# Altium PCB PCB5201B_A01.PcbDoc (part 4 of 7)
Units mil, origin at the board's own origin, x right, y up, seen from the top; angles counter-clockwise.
Board outline 4527.56 x 2362.2 mil, 6 copper layers (Top Layer, GND Layer 2, Signal Layer 3, Signal Layer 4, VCC Layer 5, Bottom Layer), stack 61.221 mil thick; 361 components, 250 nets, 1223 pads, 1068 vias.
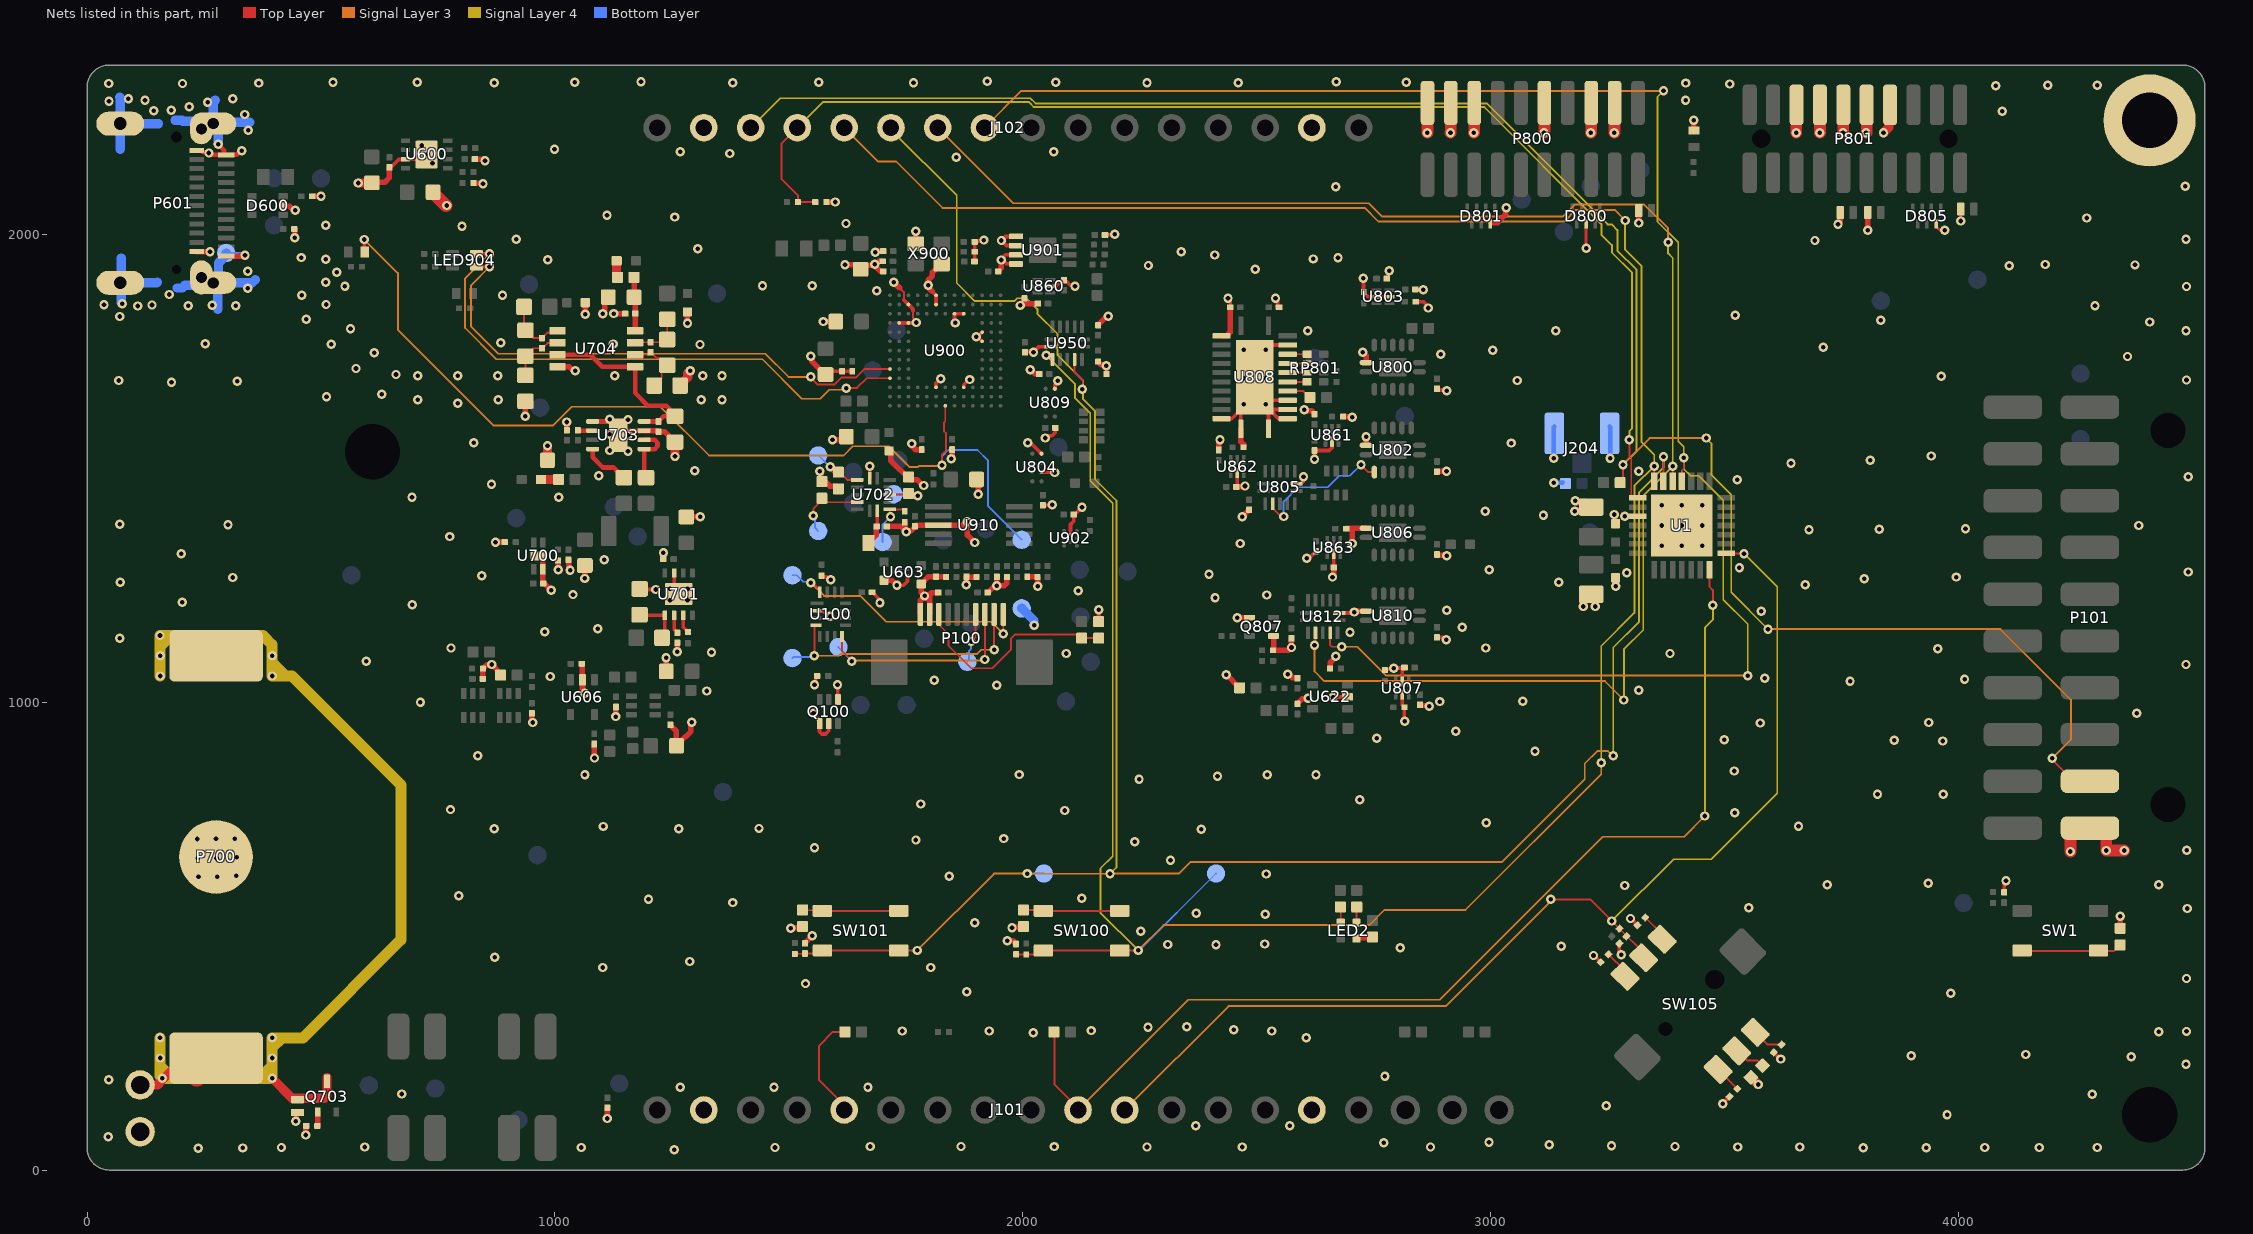
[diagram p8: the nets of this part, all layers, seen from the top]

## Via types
v1: diameter 20, hole 9.84, Top Layer to Bottom Layer, tented both sides, 1068 vias

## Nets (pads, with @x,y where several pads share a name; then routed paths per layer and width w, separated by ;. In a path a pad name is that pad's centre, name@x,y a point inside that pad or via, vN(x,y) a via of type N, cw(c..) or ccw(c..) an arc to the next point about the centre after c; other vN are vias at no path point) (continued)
GND: C1.2 C2.2 C3.2 C4.2 C8.2 C102.2 C103.2 C104.2 C106.2 C143.2 C144.2 C600.2 C602.2 C607.2 C608.2 C609.2 C610.2 C611.2 C621.2 C625.2 C632.2 C635.2 C638.2 C641.2 C652.2 C653.2 C655.2 C660.2 C673.2 C674.2 C700.2 C701.2 C702.2 C703.2 C705.2 C706.2 C707.2 C708.2 C714.2 C720.2 C724.2 C728.2 C729.2 C730.2 C731.2 C800.2 C803.2 C804.2 C805.2 C806.2 C807.2 C808.2 C809.2 C810.2 C827.2 C828.2 C860.2 C861.2 C862.2 C863.2 C864.2 C865.2 C866.2 C867.2 C868.2 C869.2 C870.2 C900.2 C901.2 C902.2 C903.2 C904.2 C905.2 C906.2 C907.2 C908.2 C909.2 C910.2 C911.2 C914.2 C921.2 C922.2 C924.2 C925.2 C926.2 C927.2 C950.2 C951.2 D600.2 D703.2 D800.6 D801.7 D805.7 D806.2 D807.2 D808.2 D809.2 J101.2 J101.15 J102.2 J102.15 J204.2 J204.3 LED900.2 M1.1 P100.1 P100.2 P101.1 P601.25@70.87,2237.01 P601.26@70.87,1896.85 P601.27@244.09,2225.39 P601.27@269.69,2237.01 P601.28@244.09,1908.46 P601.28@269.69,1896.85 P601.A1 P601.A12 P601.B1 P601.B12 P700.2 P800.3 P800.5 P800.9 P800.15 P800.17 P800.19 P801.7 P801.9 P801.11 P801.13 P801.15 Q100.1 Q100.4 Q100.5 Q807.1 Q807.4 R7.1 R104.2 R105.2 R113.1 R124.1 R125.1 R126.1 R127.1 R140.1 R141.1 R146.1 R220.1 R302.1 R602.1 R620.1 R621.1 R623.1 R628.2 R631.1 R634.1 R637.1 R640.1 R674.2 R688.2 R691.2 R703.1 R705.1 R706.1 R707.1 R708.1 R718.1 R760.1 R763.1 R767.1 R771.1 R792.1 R807.2 R808.2 R814.1 R817.1 R839.1 R850.1 R851.1 R852.1 R853.1 R930.2 R931.2 R950.2 R981.2 ST701.1 TPJ614.1 TPJ913.1 U1.3 U1.29 U100.2 U600.3 U600.9 U603.A1 U606.2 U622.2 U700.2 U700.5 U701.3 U701.9 U702.7 U703.3 U703.5 U703.9 U704.4 U800.7 U802.7 U803.2 U803.5 U804.B1 U804.D1 U805.7 U806.7 U807.2 U807.5 U808.2 U808.11 U808.12 U808.13 U808.14 U808.15 U808.16 U808.22 U808.25 U809.D1 U810.7 U812.7 U860.2 U861.2 U862.2 U863.2 U900.C5 U900.C8 U900.H3 U900.J3 U900.K11 U900.K12 U900.L5 U900.L6 U900.M8 U900.M11 U900.N8 U901.1 U901.2 U901.3 U901.4 U902.B2 U910.3 U950.7 X900.2 X900.4 | length 9104.5
  Top Layer w3.94: 1737.2,1885.83 1746.06,1876.97 1746.06,1860.24 ; 1765.75,1837.57 1765.75,1821.85 v1@1772.64,1814.96
  Top Layer w5.91: v1(3204.72,1970.47) D800.6@3204.72,2023.03 ; D805.7@3952.76,2023.03 3952.76,2017.72 3960.63,2009.84 v1@3978.35,2009.84
  Top Layer w7.87: C600.2@646.33,2143.75 646.33,2144.54 648.7,2146.9 652.81,2146.9 666.24,2160.33 679.42,2160.33 U600.3@680.4,2161.32 U600.9@715.84,2161.32 ; R703.1@1185.22,1242.35 1186.43,1241.14 v1(1215.55,1241.14) ; U701.9@1249.02,1243.11 1254.92,1249.02 U701.3@1254.92,1276.57 ; v1(1552.99,976.38) 1552.99,973.18 1565.94,960.23 Q100.4@1565.94,954.32 1565.94,937.01 1570.87,932.09 1578.73,932.09 1585.62,938.98 Q100.5@1585.62,954.32 ; v1(1555.03,1037.53) 1555.03,1040.81 1557.96,1043.74 1557.96,1054.02 1560.32,1056.38 R141.1@1560.71,1056.38 ; U100.2@1558.66,1195.87 1573.05,1195.87 1585.07,1183.85 v1(1588.35,1183.85) ; R140.1@1570.4,1270.69 1570.4,1270.29 1572.76,1267.93 1581.03,1267.93 1586.87,1262.08 v1(1590.16,1262.08) ; C907.2@1578.74,1700.79 1585.63,1707.68 C924.2@1614.17,1707.68 C925.2@1635.83,1707.68 ; v1(1604.33,1037.39) 1604.82,1036.9 1604.82,1005.99 Q100.1@1605.31,1005.5 ; U702.7@1673.23,1478.74 v1(1673.23,1504.92) v1@1679.13,1504.92 ; C104.2@1678.07,1235.18 1678.86,1235.18 1692.63,1221.41 1692.63,1215.07 v1(1694.95,1212.75) ; v1(1731.3,1250) 1745.08,1250 1753.94,1258.86 U603.A1@1753.94,1269.69 ; U900.K12@1736.22,1811.02 U900.K11@1755.91,1811.02 1771.65,1811.02 v1(1772.64,1812.01) v1@1772.64,1814.96 ; 1746.06,1860.24 U900.M11@1755.91,1850.39 1765.75,1840.55 1765.75,1837.57 ; v1@1785.43,1460.63 v1(1788.39,1463.58) ; 1806.5,1878.35 1814.76,1870.08 U900.N8@1814.96,1870.08 U900.M8@1814.96,1850.39 ; U900.C8@1814.96,1673.23 1814.96,1682.09 v1(1824.8,1691.93) ; v1(1856.3,1811.02) 1854.33,1812.99 U900.L6@1854.33,1830.71 U900.L5@1874.02,1830.71 ; U900.C5@1874.02,1673.23 1874.02,1679.13 v1@1884.84,1689.96 ; C910.2@1897.01,1942.24 1897.37,1942.6 1897.37,1962.86 R930.2@1897.68,1963.17 ; R930.2@1897.72,1963.13 R930.2@1897.68,1963.17 ; v1@1898.57,1781.5 v1(1900.59,1781.5) 1901.58,1781.5 v1@1902.56,1782.48 ; U900.H3@1913.39,1771.65 v1@1902.56,1782.48 ; U900.J3@1913.39,1791.34 1904.53,1782.48 v1@1902.56,1782.48 ; v1(1917.32,1988.19) 1915.35,1986.22 1899.61,1986.22 R931.2@1897.64,1984.25 1897.68,1984.21 R930.2@1897.68,1963.17 ; v1@1954.72,1944.88 1958.01,1944.88 1965.48,1937.41 1985.6,1937.41 U901.4@1986.01,1937.01 ; v1@1954.72,1948.16 1963.25,1956.69 U901.3@1986.01,1956.69 ; U901.2@1986.01,1976.38 1985.68,1976.7 1965.23,1976.7 v1(1954.72,1987.2) 1963.26,1995.74 1985.68,1995.74 U901.1@1986.01,1996.06 ; C911.2@2004.92,1748.03 2005.91,1747.05 2007.59,1747.05 2010.55,1750 2021.86,1750 v1(2023.31,1748.56) ; v1@2016.73,1553.15 2018.7,1553.15 U804.D1@2040.35,1531.5 ; v1@2023.62,1750 2024.14,1750 2033.98,1759.84 U950.7@2060.63,1759.84 ; U804.B1@2040.35,1492.13 2067.91,1492.13 v1(2068.9,1491.14) ; C804.2@2043.31,1421.26 2062.01,1421.26 v1(2062.99,1422.24) ; v1(2048.23,1564.96) 2053.15,1569.88 2062.99,1569.88 2069.88,1576.77 C810.2@2069.88,1586.61 ; U860.2@2059.06,1889.76 2071.85,1889.76 2084.65,1902.56 C862.2@2088.58,1902.56 2088.58,1901.77 2090.94,1899.41 2094.25,1899.41 2102,1891.66 2109.69,1891.66 v1(2112.01,1889.34) ; U809.D1@2068.9,1670.28 2069.12,1670.5 2069.12,1678.36 2075.16,1684.4 v1(2075.16,1687.68) ; U902.B2@2102.36,1358.27 2102.36,1379.92 2109.25,1386.81 C914.2@2109.25,1399.61 ; C914.2@2109.25,1401.57 C914.2@2109.25,1399.61 ; v1(2126.97,1417.32) C914.2@2109.25,1399.61 ; C951.2@2176.08,1999.15 2176.77,1999.85 2196.34,1999.85 v1(2197.04,2000.55) ; R981.2@2179.13,1701.77 v1(2179.15,1719.66) ; U808.11@2425.39,1606.3 2446.85,1606.3 U808.25@2466.54,1625.98 ; v1(2438.98,1864.17) 2443.9,1859.25 C808.2@2443.9,1844.49 ; C860.2@2456.69,1460.63 2458.66,1462.6 U862.2@2458.66,1490.16 ; U808.12@2466.54,1584.84 U808.25@2466.54,1625.98 ; U808.25@2497.05,1753.94 2506.89,1763.78 U808.22@2566.73,1763.78 ; U808.13@2525.59,1584.84 U808.25@2525.59,1625.98 ; v1(2540.63,1863.98) 2540.63,1861.23 2545.08,1856.79 2545.08,1846.85 2547.44,1844.49 C806.2@2548.23,1844.49 ; U808.14@2566.73,1606.3 2547.24,1606.3 U808.25@2527.56,1625.98 ; U808.15@2566.73,1625.98 U808.25@2527.56,1625.98 ; U808.16@2566.73,1645.67 2504.92,1645.67 U808.25@2496.06,1636.81 ; U805.7@2585.04,1467.32 2595.28,1467.32 2599.41,1471.46 2599.41,1481.3 v1(2600.39,1482.28) ; v1(2607.28,1308.07) 2612.2,1308.07 C867.2@2626.97,1322.83 ; v1(2624.02,1519.69) C864.2@2624.02,1538.39 2655.51,1538.39 2661.42,1544.29 U861.2@2661.42,1557.09 ; v1(2663.67,1011.11) 2664.02,1011.46 2694.53,1011.46 U622.2@2694.88,1011.81 ; C866.2@2665.35,1288.39 U863.2@2665.35,1316.93 ; U812.7@2676.58,1190.94 2706.69,1190.94 v1(2708.66,1192.91) ; v1(2728.35,1906.5) 2728.84,1906 2728.84,1877.46 R807.2@2729.33,1876.97 ; R807.2@2731.69,1873.62 2738.19,1867.13 U803.2@2756.89,1867.13 ; U803.2@2758.86,1867.13 U803.5@2784.45,1867.13 ; R808.2@2774.61,1068.9 2776.57,1070.87 2788.39,1070.87 v1@2790.35,1072.83 ; C869.2@2778.31,1905.63 2778.78,1905.63 2781.14,1907.99 2781.14,1919.92 v1(2783.46,1922.24) ; v1(2793.31,1072.83) 2793.98,1073.5 2815.83,1073.5 C870.2@2816.5,1074.17 ; U807.5@2811.54,1016.73 2811.54,993.66 2815.04,990.16 R814.1@2816.93,990.16 ; U807.2@2811.54,1044.29 2811.54,1070 2813.39,1071.85 C870.2@2816.93,1071.85 ; R814.1@2816.22,989.37 2816.22,960.42 v1(2816.93,959.71) ; C807.2@2839.57,1882.87 2840.15,1882.29 2856.11,1882.29 v1(2856.69,1881.71) ; R817.1@2840.55,1856.3 2856.91,1856.3 2867.13,1846.09 v1(2867.13,1842.9) ; C827.2@2885.83,1138.78 2900.59,1138.78 v1(2905.51,1133.86) ; C803.2@2885.83,1670.28 2885.83,1670.1 2888.19,1667.74 2905.09,1667.74 v1(2906.5,1666.34) ; v1@2905.61,1493.63 v1(2906.13,1494.14) ; v1(3220.47,458.66) 3221.49,458.66 R124.1@3235.74,444.4 ; C106.2@3275.81,484.47 3275.81,464.35 v1(3279.53,460.63) ; v1(3299.49,537.68) 3300.5,537.68 R127.1@3314.76,523.42 ; v1(3497.08,141.73) 3497.08,142.75 R125.1@3511.33,157 ; R126.1@3605.82,251.49 3620.08,237.23 v1(3621.09,237.23) ; v1@4005.87,2028.91 D808.2@4005.84,2054.37 ; C8.2@4098.43,593.5 4098.43,614.17 v1(4102.36,618.11) ; U808.25@2466.54,1625.98 2477.36,1636.81 U808.25@2496.06,1636.81 ; U808.25@2496.06,1636.81 2506.89,1625.98 U808.25@2525.59,1625.98 ; U808.25@2525.59,1625.98 U808.25@2527.56,1625.98
  Top Layer w9.84: P601.B12@234.25,2180.12 234.65,2179.72 245.08,2179.72 248.56,2176.24 258.51,2176.24 v1(260.45,2174.3) ; v1@262.14,2172.36 265.14,2172.36 266.83,2170.67 P601.A1@292.6,2170.67 ; v1(280.64,2193.3) 280.64,2192.48 292.6,2180.51 P601.A1@292.6,2170.67 ; v1(330.62,2179.03) 327.87,2179.03 319.51,2170.67 297.64,2170.67 P601.A1@297.24,2170.28 ; U703.5@1080.71,1600.39 v1@1112.21,1600.39 ; R302.1@1580.54,2069.45 1580.63,2069.54 1599.07,2069.54 v1(1599.17,2069.64) 1596.46,2072.35 v1@1596.46,2072.83 ; v1@2162.4,1196.85 2162.72,1196.53 2162.72,1172.56 R146.1@2162.68,1172.52 ; C868.2@2849.45,994.61 2850.83,993.23 2867.68,993.23 v1(2869.09,991.81) ; C3.2@3198.82,1217.3 3212.6,1231.08 C3.2@3215.55,1231.08 ; C1.2@3216.51,1410.41 C1.2@3231.3,1425.2 ; C3.2@3224.41,1224.41 C3.2@3225.39,1225.39 ; v1(3267.72,1248.03) C4.2@3267.72,1266.21 ; v1(3287.4,1397.64) U1.3@3319.88,1397.64 ; P601.A1@292.6,2170.67 296.85,2170.67 P601.A1@297.24,2170.28 ; P601.A1@292.6,2170.67 293,2170.28 P601.A1@297.24,2170.28
  Top Layer w10.63: v1@3033.74,2054.91 v1(3033.74,2057.12)
  Top Layer w11.81: P601.B1@234.25,1963.58 v1(262.8,1963.58) ; P601.A12@297.24,1953.74 324.8,1953.74 325.2,1954.14 336.03,1954.14 v1(337.6,1955.71) ; D600.2@419.16,2061.96 420.64,2060.48 432.81,2060.48 441.24,2052.05 v1(444.79,2052.05) ; R621.1@442.91,2011.81 443.01,2011.81 443.41,2011.42 443.41,1993.6 v1(443.9,1993.11) ; v1(445.87,104.33) 447.43,105.9 447.43,121.06 449.4,123.03 D703.2@449.8,123.03 ; v1(467.52,74.8) 467.82,75.1 467.82,94.09 468.21,94.49 R792.1@468.5,94.49 ; R620.1@481.25,2081.91 481.35,2081.8 499.89,2081.8 v1(500,2081.69) ; C611.2@611.22,2108.27 614.73,2111.78 636.38,2111.78 646.33,2121.73 C600.2@646.33,2143.75 ; R602.1@826.07,2110.14 826.07,2109.74 826.47,2109.35 845.37,2109.35 v1(846.38,2108.34) ; C602.2@829.02,2161.32 846.74,2161.32 v1(850.68,2157.38) ; C610.2@845.47,1050.2 845.47,1070.87 R623.1@846.46,1071.85 855.32,1080.71 v1(865.16,1080.71) 883.86,1062.01 R628.2@883.86,1058.07 ; v1(873.03,1342.52) v1(873.03,1342.52) 892.83,1342.47 R763.1@892.88,1342.43 ; v1(937.01,1611.22) R767.1@937.01,1643.7 ; C621.2@950.79,976.38 950.79,958.66 v1(952.76,956.69) ; U700.5@964.57,1312.99 970.47,1312.99 974.41,1309.06 U700.2@974.41,1284.45 974.41,1254.92 C708.2@975.39,1253.94 977.36,1253.94 v1(992.13,1239.17) ; U704.4@1005.69,1717.52 1030.51,1717.52 1039.37,1708.66 v1(1043.31,1708.66) ; R760.1@1006.81,1303.28 R760.1@1006.81,1303.28 v1(1006.89,1283.46) v1(1006.89,1283.46) ; v1(1025.45,1599.2) 1025.52,1599.13 1025.52,1581.77 C728.2@1025.59,1581.69 ; C701.2@1028.89,1304.6 1029.28,1304.21 1029.28,1287.9 1032.48,1284.7 v1(1032.48,1282.48) ; R674.2@1057.49,1082.27 1057.88,1082.27 1058.28,1081.88 1058.28,1049.01 U606.2@1059.06,1048.23 1059.06,1024.6 v1(1063.98,1019.69) ; v1(1063.98,1264.76) 1064.12,1264.91 1064.12,1292.18 C700.2@1064.27,1292.33 ; v1(1064.96,1829.72) C720.2@1064.96,1854.33 ; C660.2@1084.15,910.82 1084.4,910.57 1084.4,881.15 v1(1084.65,880.91) ; v1(1102.36,1830.71) 1106.3,1834.65 1106.3,1858.27 C731.2@1114.17,1866.14 ; v1@1112.21,110.24 C706.2@1112.21,132.87 ; v1@1112.21,1600.39 v1(1117.13,1605.32) ; v1(1125.86,1831.06) C730.2@1150.47,1831.06 ; v1(1129.92,969.49) 1130.17,969.74 1130.17,989.77 C674.2@1130.42,990.02 ; U703.9@1135.83,1570.87 U703.9@1145.67,1580.71 ; v1(1156.43,1604.44) 1154.87,1602.87 1154.87,1600.39 1149.61,1600.39 1145.67,1596.46 U703.9@1145.67,1580.71 ; C702.2@1232.09,1305.96 v1(1232.09,1319.72) ; v1(1237.73,1095.35) 1237.93,1095.16 1237.93,1066.35 C625.2@1238.12,1066.16 ; C673.2@1247.44,950.59 1260,938.03 C655.2@1260,907.93 ; R718.1@1256.89,1556.1 1234.25,1578.74 C729.2@1221.46,1578.74 1219.49,1580.71 U703.3@1190.95,1580.71 U703.9@1145.67,1580.71 ; C655.2@1260,906.95 C655.2@1260,907.93 ; v1(1261.81,1108.27) C705.2@1261.8,1127.12 ; C703.2@1280.92,1396.12 1281.19,1396.39 1310.76,1396.39 v1(1311.02,1396.65) ; v1(1283.46,1810.04) C724.2@1283.46,1834.65 ; v1(1292.37,957.4) 1290.81,955.83 1290.81,937.76 1279.26,926.21 1278.28,926.21 C655.2@1260,907.93 ; v1@1501.97,517.72 1502.55,518.3 1527.16,518.3 R105.2@1529.53,520.67 ; v1(1503.94,516.73) v1@1504.92,517.72 ; C103.2@1534.88,484.5 1534.88,485.29 1550.12,500.53 v1(1550.46,500.53) ; v1(1547.38,1740.01) 1548.95,1738.44 1548.95,1729.59 1577.76,1700.79 C907.2@1578.74,1700.79 ; v1(1566.65,1494.11) 1566.65,1491.9 1568.62,1489.92 1568.62,1477.54 R705.1@1574.53,1471.63 ; v1(1573.82,1813.98) C900.2@1600.39,1813.98 ; R705.1@1579.72,1470.47 1579.72,1466.44 1580.43,1465.73 1584.47,1465.73 1587.85,1462.35 1603.14,1462.35 R706.1@1609.05,1456.44 ; v1(1593.5,1561.02) 1616.14,1561.02 C902.2@1623.03,1567.91 ; v1(1620.32,1935.63) 1643.94,1935.63 C903.2@1653.79,1925.79 ; C903.2@1657.48,1929.13 1662.56,1934.22 1682.02,1934.22 v1(1684.15,1936.34) ; v1(1685.21,1961.93) 1687.42,1961.93 1689.52,1964.03 1701.28,1964.03 C906.2@1701.67,1964.42 ; C905.2@1701.2,1942.98 1700.8,1942.59 1692.61,1942.59 1686.36,1936.34 v1(1684.15,1936.34) ; C904.2@1701.67,1921.35 1701.28,1921.74 1695.16,1921.74 1685.72,1931.19 1685.72,1934.78 v1(1684.15,1936.34) ; C609.2@1703.74,1260.83 1720.47,1260.83 v1(1731.3,1250) ; C707.2@1709.65,1375.98 1739.87,1375.98 v1@1747.86,1368 ; C901.2@1714.57,1537.4 1718.5,1533.46 1718.5,1516.22 1758.76,1475.96 1773.79,1475.96 1786.17,1463.58 v1(1788.39,1463.58) ; v1(1724.41,1897.64) 1732.28,1889.76 1733.27,1889.76 1737.2,1885.83 ; R708.1@1748.03,1384.84 1748.03,1384.23 1747.86,1384.06 v1@1747.86,1368 ; v1(1751.01,1364.85) v1@1747.86,1368 ; v1@1751.97,1362.2 1751.97,1363.59 1754.79,1366.41 1760.9,1366.41 1769.69,1375.2 C922.2@1769.69,1375.98 ; v1(1762.8,1553.15) 1762.8,1548.23 1770.67,1540.35 C927.2@1784.45,1540.35 ; C922.2@1769.29,1375.59 C922.2@1769.69,1375.98 ; X900.4@1771.65,1980.31 v1(1771.65,2006.89) ; P100.1@1781.5,1187.99 1781.5,1218.5 v1(1790.35,1227.36) ; v1@1798.21,1891.75 1798.21,1902.57 1807.09,1911.45 1807.09,1919.29 1824.8,1937.01 X900.2@1826.77,1937.01 ; v1(1798.23,1891.73) 1798.23,1886.61 1806.5,1878.35 ; P100.2@1801.18,1187.99 1801.18,1216.54 ; C143.2@1819.84,1234.81 1819.45,1234.42 1805.28,1234.42 1801.18,1230.32 ; R637.1@1836.61,1267.72 1835.63,1268.7 C638.2@1814.96,1268.7 1799.21,1268.7 C608.2@1783.47,1252.95 1783.47,1234.25 v1(1790.35,1227.36) ; v1@1849.41,1520.67 C926.2@1849.41,1540.35 ; v1(1879.61,1251.26) v1@1879.77,1251.42 ; v1@1881.18,1252.83 v1@1879.77,1251.42 ; v1@1882.87,1386.81 v1(1881.89,1385.83) ; v1(1897.64,1341.54) 1881.89,1357.28 v1(1881.89,1385.83) ; R640.1@1901.18,1266.93 1901.18,1267.32 R640.1@1901.58,1267.72 1880.91,1267.72 C641.2@1879.92,1268.7 1879.77,1268.54 v1@1879.77,1251.42 ; C921.2@1901.57,1476.38 1905.51,1472.44 v1(1905.51,1444.88) ; C144.2@1925.18,1234.98 1925.97,1234.98 1938.44,1247.45 1943.32,1247.45 v1(1944.88,1249.02) ; C635.2@1944.88,1268.7 v1(1944.88,1249.02) ; C908.2@1947.84,1921.26 1954.72,1928.15 1954.72,1944.88 v1(1954.09,1945.52) ; R634.1@1966.54,1267.72 1966.54,1254.92 1960.63,1249.02 v1(1944.88,1249.02) ; v1(1967.52,490.16) 1979.33,490.16 C102.2@1986.22,483.27 ; v1@1977.36,516.73 1979.72,519.09 2000.46,519.09 R104.2@2001.84,520.46 ; R850.1@2003.93,1863.87 2003.53,1863.47 2003.53,1859.09 1995.08,1850.64 v1(1995.08,1848.43) 1997.29,1848.43 2001.23,1852.36 C863.2@2032.48,1852.36 ; C632.2@2009.84,1268.7 2030.51,1268.7 R631.1@2031.5,1267.72 2032.48,1266.73 v1(2032.48,1248.03) ; v1(2016.28,1710.57) 2018.5,1710.57 2026.93,1702.14 2035.22,1702.14 C909.2@2035.61,1701.75 ; R950.2@2161.42,1728.35 2161.42,1727.95 2168.14,1721.23 2177.59,1721.23 v1(2179.15,1719.66) ; C950.2@2161.42,1806.1 2161.81,1806.5 2161.81,1807.28 2178.26,1823.73 2181.25,1823.73 v1(2182.82,1825.3) ; C861.2@2419.29,1539.37 2419.69,1539.76 2419.69,1556.53 2421.96,1558.81 v1(2421.96,1561.02) ; U808.2@2425.39,1783.46 2436.02,1783.46 2443.9,1791.34 C808.2@2443.9,1844.49 ; v1(2435.15,1059.2) 2435.45,1059.2 R691.2@2463.67,1030.97 ; C860.2@2456.69,1460.63 2471.39,1460.63 2473.18,1462.41 v1(2475.39,1462.41) ; v1(2458.66,1181.1) Q807.4@2485.24,1181.1 ; U808.12@2466.54,1584.84 2466.54,1557.09 2472.44,1551.18 R852.1@2472.44,1545.28 ; v1(2469.49,1396.65) C800.2@2484.25,1411.42 ; Q807.1@2536.42,1141.73 2536.42,1112.2 R839.1@2535.43,1111.22 2568.9,1111.22 v1(2574.8,1117.13) C828.2@2574.8,1136.81 ; v1(2566.93,1059.88) 2569.15,1059.88 2576.08,1052.95 2586.99,1052.95 2587.38,1052.56 C653.2@2587.38,1051.77 ; C652.2@2587.58,996.5 2587.58,997.29 2597.59,1007.29 2608.67,1007.29 v1(2610.24,1008.86) ; v1(2602.36,1625.26) 2603.85,1623.77 2617.18,1623.77 C865.2@2623.62,1617.32 ; R688.2@2656.94,1072.15 2657.33,1072.15 2657.73,1072.54 2657.73,1084.65 2669.29,1096.21 v1(2669.29,1098.43) ; v1(2662.4,1267.72) 2665.35,1270.67 C866.2@2665.35,1288.39 ; R851.1@2685.03,1610.72 2685.43,1610.33 2703.65,1610.33 v1(2704.72,1609.25) ; R853.1@2691.93,1371.06 2692.91,1372.05 2703.87,1372.05 ; v1(2704.72,1339.57) 2704.72,1370.94 2703.74,1371.92 2703.87,1372.05 ; v1(2708.66,1192.91) 2710.63,1194.88 U810.7@2734.25,1194.88 ; v1(2727.36,1748.03) 2734.25,1741.14 U800.7@2734.25,1726.38 ; U806.7@2734.25,1372.05 2703.87,1372.05 ; U802.7@2734.25,1549.21 v1(2734.25,1567.91) ; C809.2@2885.83,1315.94 2885.83,1315.16 2886.22,1314.76 2902.51,1314.76 2904.28,1312.99 v1(2906.5,1312.99) ; C805.2@2885.83,1493.11 2885.83,1493.23 2886.22,1493.63 2905.04,1493.63 v1@2905.96,1494.54 ; D801.7@3002.17,2025.55 3015.71,2025.55 3032.72,2042.57 3032.72,2053.89 v1@3033.74,2054.91 ; v1(3264.76,1401.57) 3266.24,1400.1 3266.24,1384.35 C2.2@3268.21,1382.38 ; v1(3316.93,2024.61) D809.2@3316.93,2051.18 ; LED900.2@3435.04,2222.44 v1(3435.04,2244.09) ; v1(3743.11,2021.65) 3748.03,2026.58 D806.2@3748.03,2047.24 ; v1(3806.76,2009.1) 3806.92,2009.26 3806.92,2047.08 D807.2@3807.09,2047.24 ; R7.1@4346.46,516.73 v1(4346.46,542.32) ; C922.2@1769.69,1375.98 1772.64,1378.94 U910.3@1819.88,1378.94 1875,1378.94 v1(1881.89,1385.83) ; v1(1790.35,1227.36) 1793.31,1230.32 1801.18,1230.32 ; v1(1790.35,1227.36) 1801.18,1216.54 ; 1801.18,1216.54 1801.18,1230.31
  Top Layer w15.75: v1(3180.12,1408.46) 3180.93,1409.28 3207.51,1409.28 C1.2@3215.55,1417.32 3204.72,1428.15 3185.21,1428.15 3182.25,1431.1 v1(3181.1,1431.1) ; v1(3224.41,1204.72) C3.2@3224.41,1224.41
  Top Layer w19.68: v1(579.56,2110.21) 579.62,2110.27 608.32,2110.27 C611.2@608.85,2110.8 ; C607.2@739.46,2089.47 C607.2@739.46,2090.45 ; v1@766.86,2062.07 768.64,2062.07 v1(768.7,2062.01) ; C714.2@984.25,1517.72 v1(984.25,1548.23) ; v1(1256.89,1525.59) R718.1@1256.89,1556.1 ; R771.1@1267.72,1677.17 1267.72,1678.15 1284.29,1694.72 1284.29,1703.5 1289.37,1708.58 v1(1289.37,1708.66) ; v1(3198.82,1204.72) C3.2@3198.82,1217.3 ; R113.1@3556.76,198.29 3557.11,198.29 3572.54,182.86 v1(3572.62,182.86) ; v1(3840.55,2217.52) 3852.36,2229.33 3852.36,2275.06 P801.7@3854.53,2277.22
  Top Layer w25: v1(2864.76,2217.52) 2865.55,2218.31 P800.19@2865.55,2281.5 ; v1(2914.76,2217.52) 2915.55,2218.31 P800.17@2915.55,2281.5 ; v1(2964.76,2217.52) 2965.55,2218.31 P800.15@2965.55,2281.5 ; v1(3114.76,2217.52) 3115.55,2218.31 P800.9@3115.55,2281.5 ; v1(3214.76,2217.52) 3215.55,2218.31 P800.5@3215.55,2281.5 ; v1(3264.76,2217.52) 3265.55,2218.31 P800.3@3265.55,2281.5 ; v1(3653.98,2217.52) 3653.98,2276.68 P801.15@3654.53,2277.22 ; v1(3703.94,2217.52) 3704.92,2217.52 3704.53,2217.91 P801.13@3704.53,2277.22 ; v1(3753.94,2217.52) 3754.92,2217.52 3754.53,2217.91 P801.11@3754.53,2277.22 ; v1@3804.53,2217.91 P801.9@3804.53,2277.22 ; v1(4240.16,681.1) 4240.16,718.6 4252.66,731.1 P101.1@4281.89,731.1 4319.09,731.1 4316.93,728.94 v1(4316.93,683.07) v1(4355.32,683.07)
  Top Layer w27.56: C607.2@739.46,2089.47 v1@766.86,2062.07
  Bottom Layer w9.84: v1(3135.83,1469.49) 3153.54,1469.49 R220.1@3154.53,1470.47 ; v1(3135.83,1521.65) 3135.83,1588.58 J204.2@3136.81,1589.57 ; J204.3@3254.92,1589.57 3255.91,1588.58 v1(3255.91,1521.65)
  Bottom Layer w11.81: TPJ614.1@299.21,1957.68 299.61,1957.28 336.03,1957.28 v1(337.6,1955.71)
  Bottom Layer w19.68: TPJ913.1@1998.09,1200.83 2024.61,1174.31 v1(2024.61,1164.37)
  Bottom Layer w20: 69.88,2293.31 70.87,2292.32 P601.25@70.87,2237.01 ; 70.87,2182.09 P601.25@70.87,2237.01 ; v1@72.83,1854.33 72.83,1894.88 P601.26@70.87,1896.85 ; 72.83,1949.8 72.83,1898.82 P601.26@70.87,1896.85 ; 149.61,1897.64 148.82,1896.85 P601.26@70.87,1896.85 ; 152.56,2237.2 152.36,2237.01 P601.25@70.87,2237.01 ; 187.99,2244.09 203.06,2244.09 204.93,2242.22 264.47,2242.22 P601.27@269.69,2237.01 ; 192.91,1885.83 203.23,1885.83 209.04,1891.64 264.47,1891.64 P601.28@269.69,1896.85 P601.28@280.95,1896.85 ; 273.62,2287.4 269.69,2283.46 P601.27@269.69,2237.01 ; 279.53,1840.55 P601.28@279.53,1887.01 ; v1@280.51,2193.9 280.51,2226.18 P601.27@269.69,2237.01 ; TPJ614.1@297.24,1960.63 297.24,1955.52 280.95,1939.23 P601.28@280.95,1896.85 ; 347.44,2240.16 272.83,2240.16 P601.27@269.69,2237.01 ; 359.25,1903.54 352.56,1896.85 P601.28@280.95,1896.85
  other v1: 1255,43.36 237.28,46.31 332.68,47.24 3797.32,47.29 3932.16,47.29 415.43,48.28 1056.18,48.28 1470.55,48.28 4057.16,48.28 4173.3,48.28 4297.32,48.28 593.58,49.26 2265.82,49.26 2469.56,49.26 2872.12,49.26 3528.62,49.26 3661.49,49.26 1674.29,50.25 1868.19,50.25 2067.91,50.2 3394.76,50.25 3258.93,52.21 3126.06,54.18 2771.73,58.12 2997.12,59.1 45.35,70.92 2370.08,94.49 2570.87,94.49 1112.2,110.24 3976.38,118.11 3248.03,137.8 672.78,162.67 4286.42,162.4 1267.72,177.17 1468.5,177.17 1669.29,177.17 46.34,192.96 2774.61,200.79 4487.28,226.43 4370.08,242.13 3899.9,244.07 4144.97,247.02 2606.59,282.46 2022.57,293.44 4429.13,295.28 4488.27,296.31 1742.42,297.22 1928.44,297.22 2532.77,297.22 2146.94,298.2 2451.08,300.17 2268.01,305.09 2350.68,306.08 3984.54,377.93 1880.21,380.88 1535.91,398.67 4488.27,409.5 1102.36,433.07 1803.44,433.05 1288.68,445.84 871.35,454.7 2807.38,475.37 3151.86,478.32 2413.39,481.3 2310.33,482.26 2518.01,483.24 2252.26,510.8 1977.36,517.72 1897.93,528.52 2518.99,547.22 2371.35,549.19 4490.23,559.1 3552.45,561 1380.21,571.83 1200.09,578.72 2126.27,580.68 794.58,586.59 3287.4,608.27 3720.47,610.24 4429.13,610.24 3936.31,613.16 238.19,626.97 278.54,626.97 1842.81,627.93 318.9,628.94 2520.96,632.85 2316.23,662.38 236.22,666.34 276.57,666.34 319.88,668.31 4489.17,684.06 1555.12,688.98 2239.46,701.75 1771.94,705.68 235.24,707.68 275.59,708.66 315.94,708.66 1959.65,708.66 2381.89,728.35 870.37,729.31 1265.05,729.31 1436.31,730.29 1103.13,734.58 3658.75,735.21 2991.43,742.1 3522.64,763.78 2089.86,768.68 776.86,770.64 1782.48,782.48 2720.47,791.34 3827.76,803.15 3968.5,803.15 2248.95,835.8 2416.63,841.51 1064.27,845.45 1993.11,845.47 2522.93,845.45 2627.26,845.45 3521.63,853.17 834.94,885.8 3095.47,895.67 3967.52,917.32 3863.68,918.76 3500,920.28 2757.18,923.2 2926.25,938.23 3577.06,955.68 3937.01,956.69 4381.89,976.38 712.6,1000 2891.93,1001.57 3069.19,1001.94 1324.89,1024.05 3317.43,1025.45 1944.82,1036.59 3768.99,1045.25 1810.96,1047.41 4013.78,1049.21 3586.61,1051.18 990.45,1055.09 4487.28,1080.76 596.46,1087.6 2093.5,1104.33 3384.15,1104.31 1334.94,1107.26 3956.69,1114.17 777.85,1116.12 2990.45,1116.12 69.88,1136.81 2699.8,1149.61 978.64,1150.57 1091.82,1157.46 2940.25,1160.41 3579.15,1194.46 2906.5,1196.85 2162.76,1198.19 695.17,1208.64 203.05,1213.56 1246.06,1218.5 1283.46,1218.5 2411.42,1223.43 2521.65,1229.33 1038.68,1230.29 2119.09,1238.19 1246.06,1243.11 1283.46,1243.11 3673.23,1250.98 3145.96,1256.87 70.87,1256.89 3799.21,1263.78 311.31,1266.71 3996.06,1267.72 843.79,1270.64 2398.56,1273.79 3291.34,1276.57 4492.2,1278.59 2997.34,1283.44 3532.48,1287.4 1105.6,1305.09 201.08,1317.89 3366.14,1334.65 3409.45,1334.65 3452.76,1334.65 2465.55,1339.57 774.9,1354.31 3681.1,1369.09 3831.69,1370.08 4015.75,1371.06 3366.14,1377.95 3409.45,1377.95 3452.76,1377.95 4385.83,1377.95 301.18,1379.92 69.88,1380.91 3113.48,1399.58 2989.07,1408.53 3366.14,1421.26 3409.45,1421.26 3452.76,1421.26 694.64,1438.04 1008.24,1438.58 864.46,1466.51 3527.56,1475.39 4492.2,1482.33 1093.79,1484.23 3316.93,1494.09 1299.17,1494.94 3642.72,1510.83 3812.3,1517.69 1847.44,1520.67 3942.91,1526.57 1156.43,1536.53 1117.13,1538.39 3044.55,1554.23 826.77,1555.12 2010.83,1555.12 1156.43,1570.98 1117.13,1572.83 2472.44,1636.81 2519.68,1636.81 792.1,1639.1 706.69,1646.65 878.94,1646.65 1312.99,1646.65 1357.28,1646.65 511.81,1653.54 629.92,1658.46 180.41,1684.03 321.16,1686 67.91,1687.99 3057.38,1687.97 4488.27,1689.03 1886.81,1689.96 2472.44,1692.91 2519.68,1692.91 3963.58,1696.85 706.69,1697.83 792.32,1697.83 877.95,1697.83 1127.95,1697.83 1315.94,1697.83 1357.28,1697.83 660.43,1700.79 574.8,1713.58 4362.2,1739.17 2893.7,1744.09 614.17,1747.05 3005.21,1752.93 2472.44,1753.94 2519.68,1753.94 3711.56,1759.3 521.65,1765.75 1310.3,1764.9 252.26,1766.71 1124.6,1765.98 884.42,1768.68 2609.25,1794.29 3139.76,1794.29 4487.28,1794.34 562.99,1798.23 4409.74,1812.97 3834.65,1816.93 468.5,1818.9 69.88,1824.8 3523.62,1827.76 107.88,1847.16 216.54,1847.44 317.91,1847.44 4292.61,1847.42 138.78,1849.41 267.33,1849.13 36.03,1850.12 510.83,1850.39 75.4,1852.08 458.66,1870.08 888.08,1870.05 175.8,1871.77 1687.99,1879.92 343.12,1885.55 4488.27,1888.83 551.18,1889.76 1443.9,1890.75 1550.2,1890.75 509.84,1897.64 533.37,1919.42 343.5,1921.26 2497.34,1926.16 2269.01,1933.79 4109.25,1933.07 4378.24,1935.01 4186.31,1936 984.54,1945.84 509.84,1946.85 2621.06,1947.83 457.68,1950.79 2674.36,1950.12 2410.71,1956.31 2338.89,1963.32 1305.41,1969.46 3693.9,1987.2 917.61,1990.13 4487.28,1990.21 3971.46,2008.86 801.47,2017.69 509.84,2019.69 1622.34,2023.6 4005.91,2028.88 4274.9,2035.41 1256.19,2037.38 1111.51,2041.31 2669.29,2102.36 4485.31,2103.4 738.47,2152.46 1858.27,2165.35 728.04,2171.93 1374.02,2173.23 1267.72,2177.17 2066.93,2177.17 999.31,2182.06 715.34,2190.34 3803.15,2217.52 344.1,2223.15 337.21,2256.61 4094.49,2263.78 142.33,2264.49 179.73,2265.47 218.12,2273.34 257.49,2283.19 46.86,2285.15 123.63,2287.12 3417.32,2287.4 88.35,2290.36 311.44,2290.24 4080.79,2317.96 4192.01,2318.95 4297.32,2318.95 46.34,2322.88 203.82,2322.88 3511.89,2321.9 367.2,2323.87 3417.4,2323.87 870.08,2324.8 1380,2324.85 1766.81,2324.85 2265.82,2324.85 2460.71,2324.85 525.67,2325.84 705.79,2325.84 1042.32,2325.79 1564.05,2325.84 2070.94,2325.84 2819.96,2325.84 1184.13,2326.82 2670.35,2326.82 1924.29,2327.81
JS_A: R125.2 SW105.1 | length 58.4
  Top Layer w3.94: SW105.1@3487.02,215.14 3528.04,174.12 R125.2@3528.04,173.71
JS_B: R126.2 SW105.3 | length 67.1
  Top Layer w3.94: SW105.3@3566.36,294.48 3592.64,268.19 R126.2@3622.52,268.19
JS_C: R127.2 SW105.6 | length 61.3
  Top Layer w3.94: R127.2@3331.19,539.85 3367.31,503.72 SW105.6@3367.31,493.53
JS_CEN: R113.2 SW105.2 | length 68.2
  Top Layer w3.94: SW105.2@3526.69,254.81 3528.25,254.81 3548.81,234.25 3570.91,234.25 R113.2@3581.82,223.35
JS_D: R124.2 SW105.4 | length 61.6
  Top Layer w3.94: R124.2@3252.45,461.11 3287.97,425.58 SW105.4@3287.97,414.18
LED_JLINK: LED901.2 TPJ912.1 U900.A7 | length 2067.3
  Top Layer w3.94: v1(1827.76,1506.89) 1827.76,1530.07 1836.34,1538.65 1836.34,1575.08 1831.69,1579.72 1831.69,1597.44 1834.65,1600.39 U900.A7@1834.65,1633.86
  Top Layer w7.87: v1(592.55,1989.51) 592.55,1961.64 LED901.2@593.5,1962.6 ; LED901.2@593.5,1962.6 598.61,1967.7 598.43,1967.7 593.5,1962.78 LED901.2@593.5,1962.6
  Signal Layer 3 w3.94: v1@592.8,1989.26 664.37,1917.69 664.37,1796.26 869.09,1591.54 995.9,1591.54 1036.26,1631.89 1225.39,1631.89 1329.72,1527.56 1617.13,1527.56 1636.81,1547.24 1713.58,1547.24 1757.47,1503.35 1776.97,1503.35 1778.54,1504.92 1825.79,1504.92 v1(1827.76,1506.89)
  Bottom Layer w3.94: v1(1827.76,1506.89) 1827.76,1525.59 1841.54,1539.37 1903.54,1539.37 1926.18,1516.73 1926.18,1419.34 TPJ912.1@1998.09,1347.43
LED_STATUS_G: LED904.3 U900.D13 | length 1197.6
  Top Layer w3.94: v1(1623.03,1671.26) 1624.02,1672.24 1645.67,1672.24 1666.34,1692.91 U900.D13@1716.54,1692.91
  Top Layer w7.87: LED904.3@832.68,1958.66 v1(860.24,1958.66)
  Signal Layer 3 w3.94: v1(860.24,1958.66) 808.07,1906.5 808.07,1800.2 875,1733.27 1443.9,1733.27 1528.27,1648.89 1567.2,1648.89 1586.61,1668.31 1621.06,1668.31 1621.06,1669.29 v1(1623.03,1671.26)
LED_STATUS_R: LED904.4 U900.E13 | length 1133.9
  Top Layer w3.94: v1(1547.38,1695.68) 1547.38,1693.62 1561.87,1679.13 1597.44,1679.13 1612.91,1694.6 1644.41,1694.6 1662.4,1712.6 U900.E13@1716.54,1712.6
  Top Layer w7.87: LED904.4@832.68,1931.1 v1(860.24,1931.1)
  Signal Layer 3 w3.94: v1(860.24,1931.1) 820.87,1891.73 820.87,1803.15 878.94,1745.08 1450.11,1745.08 1499.51,1695.68 v1(1547.38,1695.68)
MCU_P0.0: J102.3 P101.3 R5.2 | length 4188.4
  Top Layer w3.94: R5.2@3276.08,1468.01 3283.46,1475.39 v1(3283.46,1507.87) ; v1(4201.27,880.38) 4201.27,877.3 4247.47,831.1 P101.3@4281.89,831.1
  Signal Layer 3 w3.94: v1(3283.46,1507.87) 3340.55,1564.96 v1(3461.61,1564.96) ; v1(3593.5,1156.5) 4090.55,1156.5 4241.14,1005.91 4241.14,920.25 v1@4202.76,881.86
  Signal Layer 4 w3.94: J102.3@1418.5,2228.43 1481.42,2291.34 2016.73,2291.34 2027.56,2280.51 2992.01,2280.51 3250.76,2021.76 3259.29,2021.76 3271.65,2009.4 3271.65,1965.55 3312.71,1924.49 3312.71,1537.12 v1(3283.46,1507.87) ; v1@3463.58,1566.93 3463.58,1562.15 3472.44,1553.29 3472.44,1486.37 3515.04,1443.76 3515.04,1234.96 v1(3593.5,1156.5)
MCU_P0.1: J102.4 R301.2 R302.2 U1.1 | length 2706.9
  Top Layer w3.94: J102.4@1518.5,2228.43 1484.25,2194.17 1484.25,2119.09 1519.68,2083.66 R301.2@1519.68,2069.44 ; R301.2@1520.67,2066.93 1523.18,2069.44 R302.2@1556.91,2069.45 ; v1(3297.24,1561.02) 3297.24,1525.59 3301.18,1521.65 3301.18,1442.91 3307.09,1437.01 U1.1@3319.88,1437.01
  Signal Layer 4 w3.94: J102.4@1518.5,2228.43 1573.55,2283.47 2012.79,2283.47 2023.62,2272.64 2987.2,2272.64 3237.42,2022.43 3237.42,1999.89 3259.84,1977.46 3259.84,1961.61 3303.15,1918.31 3303.15,1585.63 3297.24,1579.72 v1(3297.24,1561.02)
MCU_P0.2: C102.1 J102.5 R100.1 SW100.3 SW100.4 TPJ652.1 U1.28 U950.8 | length 6110
  Top Layer w3.94: C102.1@1986.22,461.61 1987.21,460.63 2035.43,460.63 SW100.3@2044.29,469.49 SW100.4@2207.68,469.49 v1(2247.05,469.49) ; v1(2050.5,1741.97) 2062.01,1741.97 2063.98,1740 U950.8@2063.98,1732.87 ; U1.28@3350.39,1467.52 v1(3350.39,1504.92)
  Signal Layer 3 w3.94: J102.5@1618.5,2228.43 1690.43,2156.5 1729.33,2156.5 1828.74,2057.09 2731.3,2057.09 2760.83,2027.56 3157.48,2027.56 3182.62,2052.7 3265.48,2052.7 v1(3288.19,2029.99) ; v1(2247.05,469.49) 2301.18,523.62 2741.14,523.62 2773.62,556.1 2946.85,556.1 3237.2,846.46 v1(3237.2,871.06)
  Signal Layer 4 w3.94: v1(2050.5,1741.97) 2112.35,1680.12 2112.35,1650.45 2144.68,1618.11 2144.68,1473.43 2192.63,1425.48 2192.63,670.98 2166.33,644.67 2166.33,550.21 v1(2247.05,469.49) ; v1(3237.2,871.06) 3237.2,1120.3 3308.07,1191.17 3308.07,1462.6 v1(3350.39,1504.92) 3350.39,1529.53 3322.83,1557.09 3322.83,1933.07 3288.19,1967.71 v1(3288.19,2029.99)
  Bottom Layer w3.94: v1(2247.05,469.49) 2248.04,468.49 TPJ652.1@2413.49,633.93
MCU_P0.3: C103.1 J102.6 R101.1 SW101.3 SW101.4 TPJ653.1 U1.27 U950.11 | length 4677.7
  Top Layer w3.94: R101.1@1511.97,462.92 R101.1@1512.96,461.94 1513.41,462.39 1534.24,462.39 C103.1@1534.45,462.6 ; C103.1@1534.88,462.85 1565.21,462.85 SW101.3@1571.85,469.49 SW101.4@1735.24,469.49 v1(1774.61,469.49) ; U950.11@2111.22,1732.87 2111.22,1705.44 2128.43,1688.23 2128.43,1669.52 v1(2127.83,1668.91) ; U1.27@3370.08,1467.52 v1(3370.08,1524.61)
  Signal Layer 3 w3.94: v1(1774.61,469.49) 1938.98,633.86 v1(2009.84,633.86) 2010.24,633.46 2186.38,633.46 v1(2186.78,633.06) 2187.57,633.86 2333.66,633.86 2358.27,658.46 3024.61,658.46 3201.77,835.63 3201.77,869.09 3228.35,895.67 3251.47,895.67 3261.32,885.83 v1(3262.8,885.83)
  Signal Layer 4 w3.94: J102.6@1718.5,2228.43 1718.5,2224.41 1859.25,2083.66 1859.25,1896.43 1898.12,1857.56 1981.8,1857.56 1988.13,1863.89 2008.15,1863.89 2031.5,1840.55 2031.5,1830.71 2074.8,1787.4 2074.8,1742.29 2129.48,1687.61 2129.48,1670.57 v1(2127.83,1668.91) ; v1@2128.43,1669.5 2129.36,1668.58 2129.36,1648.04 2154.53,1622.87 2154.53,1477.36 2200.51,1431.38 2200.51,646.79 v1(2186.78,633.06) ; v1(3262.8,885.83) 3262.8,1117.13 3317.91,1172.24 3317.91,1448.82 3370.08,1500.98 v1(3370.08,1524.61)
  Bottom Layer w3.94: v1(2009.84,633.86) 2009.92,633.93 TPJ653.1@2045.39,633.93
MCU_P0.4: J102.7 U1.26 U812.2 | length 3535.8
  Top Layer w3.94: v1(2624.02,1122.05) 2623.03,1122.05 2625.98,1125 U812.2@2625.98,1148.23 ; U1.26@3389.76,1467.52 v1(3389.76,1504.92)
  Signal Layer 3 w3.94: J102.7@1818.5,2228.43 1980,2066.93 2740.16,2066.93 2768.7,2038.39 3154.53,2038.39 3180.12,2063.98 3328.99,2063.98 3379.92,2013.04 v1(3379.92,1983.27) ; v1(2624.02,1122.05) 2624.02,1065.95 2644.69,1045.28 3245.08,1045.28 v1(3285.43,1004.92)
  Signal Layer 4 w3.94: v1(3285.43,1004.92) 3285.43,1113.19 3326.77,1154.53 3326.77,1441.93 v1(3389.76,1504.92) 3389.76,1949.8 3379.92,1959.65 v1(3379.92,1983.27)
MCU_P0.5: J102.8 U1.25 U812.4 | length 3832.4
  Top Layer w3.94: U812.4@2657.48,1148.23 2657.48,1122.05 2660.66,1118.87 v1(2682.61,1118.87) ; U1.25@3409.45,1467.52 3409.45,1495.35 3413.39,1499.29 v1(3413.39,1522.64)
  Signal Layer 3 w3.94: J102.8@1918.5,2228.43 1997.17,2307.09 v1(3370.08,2307.09) ; v1(2682.61,1118.87) 2715.02,1118.87 2776.52,1057.37 3549.92,1057.37 v1(3550.2,1057.09)
  Signal Layer 4 w3.94: v1(3370.08,2307.09) 3357.28,2294.29 3357.28,2027.78 3401.57,1983.49 3401.57,1558.07 3413.39,1546.26 3413.39,1498.79 3427.93,1484.25 3445.87,1484.25 3498.03,1432.09 3498.03,1219.49 3550.2,1167.32 v1(3550.2,1057.09)
MCU_P1.7: C106.1 J101.11 R111.1 SW105.5 U1.15 | length 2408.2
  Top Layer w3.94: v1(3128.94,578.74) 3213.58,578.74 v1(3259.84,532.48) 3276.07,516.25 3327.64,464.65 SW105.5@3327.64,453.85 ; U1.15@3499.02,1318.9 3499.51,1318.41 3541.83,1318.41 v1(3542.32,1317.91)
  Signal Layer 3 w3.94: J101.11@2218.5,128.43 2440.47,350.39 2904.53,350.39 3128.94,574.8 v1(3128.94,578.74)
  Signal Layer 4 w3.94: v1(3259.84,532.48) 3391.73,664.37 3472.44,664.37 3613.19,805.12 3613.19,1247.05 v1(3542.32,1317.91)
MCU_P2.0: J101.10 R304.2 U1.14 | length 2330.3
  Top Layer w3.94: R304.2@2067,295.35 2067.91,294.44 2067.91,183.07 2118.5,132.48 J101.10@2118.5,128.43 ; U1.14@3468.5,1288.39 3468.5,1247.05 3475.77,1239.78 v1(3475.77,1207.3)
  Signal Layer 3 w3.94: J101.10@2118.5,128.43 2354.25,364.17 2891.73,364.17 3240.16,712.6 3414.37,712.6 v1(3458.66,756.89)
  Signal Layer 4 w3.94: v1(3458.66,756.89) 3458.66,1159.45 3475.77,1176.56 v1(3475.77,1207.3)
MCU_P3.0: J101.5 R305.2 | length 221.9
  Top Layer w3.94: R305.2@1620.08,295.28 1594.49,295.28 1564.96,265.75 1564.96,191.93 J101.5@1622.05,134.84
N16831167: R700.1 U701.7 | length 40.1
  Top Layer w7.87: U701.7@1274.61,1186.02 1274.61,1160.35 1284.51,1150.45 R700.1@1284.51,1150.05
N16831188: C705.1 U701.6 | length 40.1
  Top Layer w7.87: U701.6@1254.92,1186.02 1254.92,1156.44 1261.79,1149.57 C705.1@1261.79,1148.78
N16831199: R702.1 R703.2 U701.5 | length 96.3
  Top Layer w7.87: R703.2@1185.04,1186.02 U701.5@1235.24,1186.02 1235.24,1148.83 R702.1@1228.96,1142.56
N16831281: R705.2 TP711.1 U702.11 | length 159.5
  Top Layer w3.94: v1(1552.03,1399.01) 1553.25,1400.23 1553.25,1414.92 1574.53,1436.2 1583.2,1427.53 1645.64,1427.53 U702.11@1646.26,1428.15
  Bottom Layer w3.94: v1(1552.03,1399.01) 1552.03,1394.66 1556.21,1390.48 1556.21,1372.92 TP711.1@1562.99,1366.14
N16831285: R706.2 TP712.1 U702.8 | length 109.5
  Top Layer w3.94: v1(1588.59,1503.69) 1591.33,1500.94 1591.33,1494.43 1594.49,1491.28 R706.2@1608.45,1491.28 ; R706.2@1609.05,1491.88 R706.2@1608.45,1491.28 ; U702.8@1646.26,1475.39 1625.53,1475.39 1609.65,1491.28 R706.2@1608.45,1491.28
  Bottom Layer w3.94: TP712.1@1562.99,1527.56 1563.85,1527.56 1587.72,1503.69 v1(1588.59,1503.69)
N16831289: R707.2 TP713.1 U702.3 | length 115.3
  Top Layer w3.94: U702.3@1715.95,1443.9 1750.32,1443.9 1752.86,1446.44 1757.42,1441.87 v1(1775.73,1441.87)
  Bottom Layer w3.94: TP713.1@1724.41,1444.88 1725.91,1443.38 1774.23,1443.38 v1(1775.73,1441.87)
N16831309: R708.2 TP714.1 U702.1 | length 111.2
  Top Layer w3.94: v1(1717.52,1396.65) 1717.52,1397.64 1715.95,1399.21 U702.1@1715.95,1412.4 1744.09,1412.4 R708.2@1748.03,1408.46
  Bottom Layer w3.94: TP714.1@1700.79,1342.52 1700.79,1379.92 v1(1717.52,1396.65)
N16831821: C707.1 L702.2 U702.14 | length 76.1
  Top Layer w7.87: C707.1@1687.01,1376.97 1688.98,1378.94 U702.14@1688.98,1409.06
  Top Layer w11.81: L702.2@1670.67,1340.55 1687.01,1356.89 C707.1@1687.01,1376.97
N17207915: LED2.4 R135.1 | length 35.7
  Top Layer w7.87: LED2.4@2713.58,495.08 2745.08,495.08 R135.1@2748.03,498.03
N17207930: LED2.3 R136.1 | length 34.1
  Top Layer w3.94: LED2.3@2713.58,528.54 2713.58,561.65 R136.1@2714.31,562.38
N17207934: LED2.2 R137.1 | length 34.3
  Top Layer w3.94: R137.1@2679.2,562.5 2680.12,561.58 LED2.2@2680.12,528.54
N17208223: P100.3 R145.1 R146.2 | length 463.6
  Top Layer w3.94: P100.3@1820.87,1187.99 1820.87,1166.34 1841.54,1145.67 1841.54,1121.06 1889.76,1072.83 1935.04,1072.83 1975.39,1113.19 1975.39,1136.81 1983.16,1144.58 2118.78,1144.58 R145.1@2126.26,1137.1 R146.2@2162.68,1137.09 ; R145.1@2125.98,1129.92 R145.1@2126.26,1129.65
N17208307: P100.10 TP150.1 U100.16 | length 576.1
  Top Layer w3.94: v1(1547.38,1255.67) 1551.41,1255.67 1562.01,1245.08 1564.57,1245.08 1566.54,1243.11 U100.16@1566.54,1235.24 ; v1(1958.66,1146.65) P100.10@1958.66,1187.99
  Signal Layer 3 w3.94: v1(1547.38,1255.67) 1575.69,1227.36 1652.96,1227.36 1708.08,1172.24 1933.07,1172.24 v1(1958.66,1146.65)
  Bottom Layer w3.94: TP150.1@1507.87,1271.65 1517.46,1271.65 1531.48,1257.64 1545.42,1257.64 v1(1547.38,1255.67)
N17208309: P100.9 TP151.1 U100.4 | length 581.9
  Top Layer w3.94: v1(1554.82,1099.41) 1554.82,1162.4 1556.79,1164.37 U100.4@1558.66,1164.37 ; v1(1938.98,1112.2) P100.9@1938.98,1187.99
  Signal Layer 3 w3.94: v1(1554.82,1099.41) 1607,1099.41 1610.93,1103.35 1902.56,1103.35 1911.42,1112.2 v1(1938.98,1112.2)
  Bottom Layer w3.94: TP151.1@1507.87,1094.49 1510.33,1096.95 1552.36,1096.95 v1(1554.82,1099.41)
N17208311: P100.8 TP152.1 U100.8 | length 485.4
  Top Layer w3.94: U100.8@1613.78,1140.75 1613.78,1110.63 1635.07,1089.34 v1(1635.07,1087.8) ; v1(1919.29,1091.54) P100.8@1919.29,1187.99
  Signal Layer 3 w3.94: v1(1635.07,1087.8) 1636.84,1089.57 v1@1919.29,1089.57
  Bottom Layer w3.94: TP152.1@1606.3,1118.11 1606.3,1117.34 1635.07,1088.57 v1(1635.07,1087.8)
N17208347: P100.7 TP153.1 | length 108.7
  Top Layer w3.94: v1(1889.76,1129.92) 1899.61,1139.76 P100.7@1899.61,1187.99
  Bottom Layer w3.94: TP153.1@1881.89,1086.61 1885.49,1090.21 1885.49,1109.9 1889.76,1114.17 v1(1889.76,1129.92)
N17209732: R104.1 SW100.1 SW100.2 | length 206.6
  Top Layer w3.94: R104.1@2001.84,555.9 2042.53,555.9 SW100.1@2044.29,554.13 2054.83,554.13 SW100.2@2207.68,554.13
N17209791: R105.1 SW101.1 SW101.2 | length 210.7
  Top Layer w3.94: R105.1@1527.56,558.07 1530.12,555.51 1570.47,555.51 SW101.1@1571.85,554.13 ; SW101.1@1570.87,553.15 SW101.1@1571.85,554.13 ; SW101.2@1735.24,554.13 SW101.1@1571.85,554.13
N17247543: R7.2 SW1.3 SW1.4 | length 223.9
  Top Layer w3.94: SW1.3@4127.88,468.5 4333.66,468.5 R7.2@4346.46,481.3
N17481376: D703.1 P700.1 Q703.3 ST701.2 | length 2490.6
  Top Layer w19.68: ST701.2@113.19,181.89 150.39,181.89 v1@160.89,192.39 ; v1(160.89,196.11) v1@160.89,192.39 ; P700.1@275.59,239.29 207.8,239.29 v1@160.89,192.39 ; v1(395.51,196.11) 438.08,153.54 507.31,153.54 512.8,159.03 Q703.3@512.8,197.83
  Top Layer w39.37: P700.1@234.13,197.83 P700.1@275.59,239.29
  Signal Layer 4 w23.62: v1@155.51,1098.43 v1@155.97,1098.88 ; v1(155.81,282.73) 155.81,222.39 ; v1(155.97,1056.11) v1@155.97,1098.88 ; 156.5,223.07 155.81,222.39 ; 360.24,195.87 368.94,195.87 369.18,196.11 ; 395.67,261.81 416.59,282.73 ; 395.67,1086.61 395.67,1084.66 424.21,1056.11 ; 155.81,222.39 182.09,196.11 ; 155.81,222.39 155.81,201.19 v1(160.89,196.11) 182.09,196.11 ; v1@155.97,1098.88 v1(155.97,1099.42) 155.97,1119.55 ; 155.97,1119.55 179.15,1142.73 ; 155.97,1119.55 155.97,1142.46 155.81,1142.62 v1(155.81,1142.73) 179.15,1142.73 ; 179.15,1142.73 375.83,1142.73 395.51,1123.03 v1(395.51,1099.42) v1(395.51,1056.11) 424.21,1056.11 ; 182.09,196.11 369.18,196.11 ; 369.18,196.11 395.51,222.44 ; 369.18,196.11 v1(395.51,196.11) 395.51,222.44 ; 395.51,222.44 v1(395.51,239.42) v1(395.51,282.73) 416.59,282.73 ; 416.59,282.73 461.17,282.73 670.82,492.38 670.82,823.59 438.29,1056.11 424.21,1056.11
  other v1: 155.97,239.42
N17481477: Q703.1 R792.2 | length 30.2
  Top Layer w11.81: R792.2@492.13,94.49 492.52,94.49 492.91,94.88 492.91,96.46 493.11,96.65 Q703.1@493.11,124.02
N17490696: C729.1 R718.2 U703.4 U704.3 U704.5 | length 412.2
  Top Layer w9.84: U704.3@1005.69,1743.11 1075.79,1743.11 1101.38,1717.52 U704.5@1171.48,1717.52 1171.48,1661.2 1198.82,1633.86 1238.33,1633.86 1244.09,1628.09 1244.09,1623.03 1255.91,1611.22 R718.2@1256.89,1611.22 1232.28,1611.22 C729.1@1221.46,1600.39 U703.4@1190.95,1600.39
N17490733: C766.2 R764.1 R765.2 U704.1 | length 134
  Top Layer w3.94: R764.1@934.06,1845.47 934.06,1798.23 R765.2@937.01,1795.28 953.74,1778.54 C766.2@972.44,1778.54 972.44,1779.33 976.77,1783.66 977.56,1783.66 984.59,1790.69 1002.09,1790.69 U704.1@1005.69,1794.29
N17490783: C766.1 R765.1 R767.2 U704.2 | length 122.3
  Top Layer w3.94: R767.2@937.01,1698.82 R765.1@937.01,1740.16 953.74,1756.89 C766.1@972.44,1756.89 972.44,1757.68 976.77,1762.01 978.69,1762.01 984.59,1767.91 1004.9,1767.91 U704.2@1005.69,1768.7
N17490812: R709.1 U703.1 U703.2 | length 132.4
  Top Layer w9.84: U703.1@1190.95,1541.34 1190.95,1484.25 R709.1@1194.88,1480.32 R709.1@1195.87,1480.32 ; U703.2@1190.95,1561.02 1213.58,1561.02 1219.35,1555.26 1219.35,1547.1 1213.58,1541.34 U703.1@1191.93,1541.34
N17490814: R710.1 U703.8 | length 103.2
  Top Layer w9.84: U703.8@1080.71,1541.34 1080.71,1523.62 1102.36,1501.97 1125.99,1501.97 1134.84,1493.11 1134.84,1492.13 1146.65,1480.32 R710.1@1147.64,1480.32
N17490860: C710.2 U703.6 | length 31.9
  Top Layer w9.84: C710.2@1049.21,1581.69 1050.2,1580.71 U703.6@1080.71,1580.71
N17490888: L700.2 R717.1 | length 37.4
  Top Layer w19.68: L700.2@970.47,1476.38 R717.1@1007.87,1476.38
N17491034: C770.2 R768.1 R769.2 U704.7 | length 106.5
  Top Layer w3.94: U704.7@1171.48,1768.7 1172.46,1769.69 C770.2@1204.72,1769.69 R769.2@1234.25,1769.69 ; R769.2@1240.16,1775.59 R768.1@1240.16,1818.9
N17491060: C770.1 R769.1 R771.2 U704.6 | length 136.9
  Top Layer w3.94: U704.6@1171.48,1743.11 1199.8,1743.11 C770.1@1204.72,1748.03 1216.54,1736.22 1224.41,1736.22 R769.1@1240.16,1720.47 1228.35,1708.66 1228.35,1692.91 R771.2@1212.6,1677.17
N17491108: L704.2 R731.2 | length 36.5
  Top Layer w19.68: L704.2@1132.16,1943.9 1131.89,1943.9 1131.89,1910.43 R731.2@1133.86,1908.46
N17491110: C730.1 C731.1 R731.1 U704.8 | length 115.7
  Top Layer w11.81: R731.1@1169.29,1908.46 C731.1@1169.29,1866.14 1172.24,1863.19 1172.24,1831.18 C730.1@1172.12,1831.06 1171.8,1830.74 1171.8,1794.61 U704.8@1171.48,1794.29
N17517174: RP801.5 U808.21 | length 41.5
  Top Layer w3.94: U808.21@2566.73,1744.09 RP801.5@2608.27,1744.09
N17517201: RP801.6 U808.20 | length 41.5
  Top Layer w3.94: U808.20@2566.73,1724.41 RP801.6@2608.27,1724.41
N17517230: RP801.7 U808.19 | length 41.5
  Top Layer w3.94: U808.19@2566.73,1704.72 RP801.7@2608.27,1704.72
N17517259: RP801.8 U808.18 | length 41.5
  Top Layer w3.94: U808.18@2566.73,1685.04 RP801.8@2608.27,1685.04
N17517278: R805.1 U808.17 | length 53.1
  Top Layer w3.94: U808.17@2566.73,1665.35 2600.39,1665.35 R805.1@2614.17,1651.57
N17517488: U802.9 U805.2 | length 304.6
  Top Layer w3.94: U805.2@2534.45,1424.61 2534.45,1415.14 v1@2550.97,1398.62 ; v1@2716.54,1507.87 v1(2723.43,1507.87) 2739.17,1492.13 U802.9@2751.97,1492.13
  Bottom Layer w3.94: v1(2558.07,1397.28) 2558.07,1429.13 2588.58,1459.65 2652.56,1459.65 2677.17,1484.25 2699.8,1484.25 v1(2723.43,1507.87)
